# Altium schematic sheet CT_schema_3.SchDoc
size 400 x 230 mm
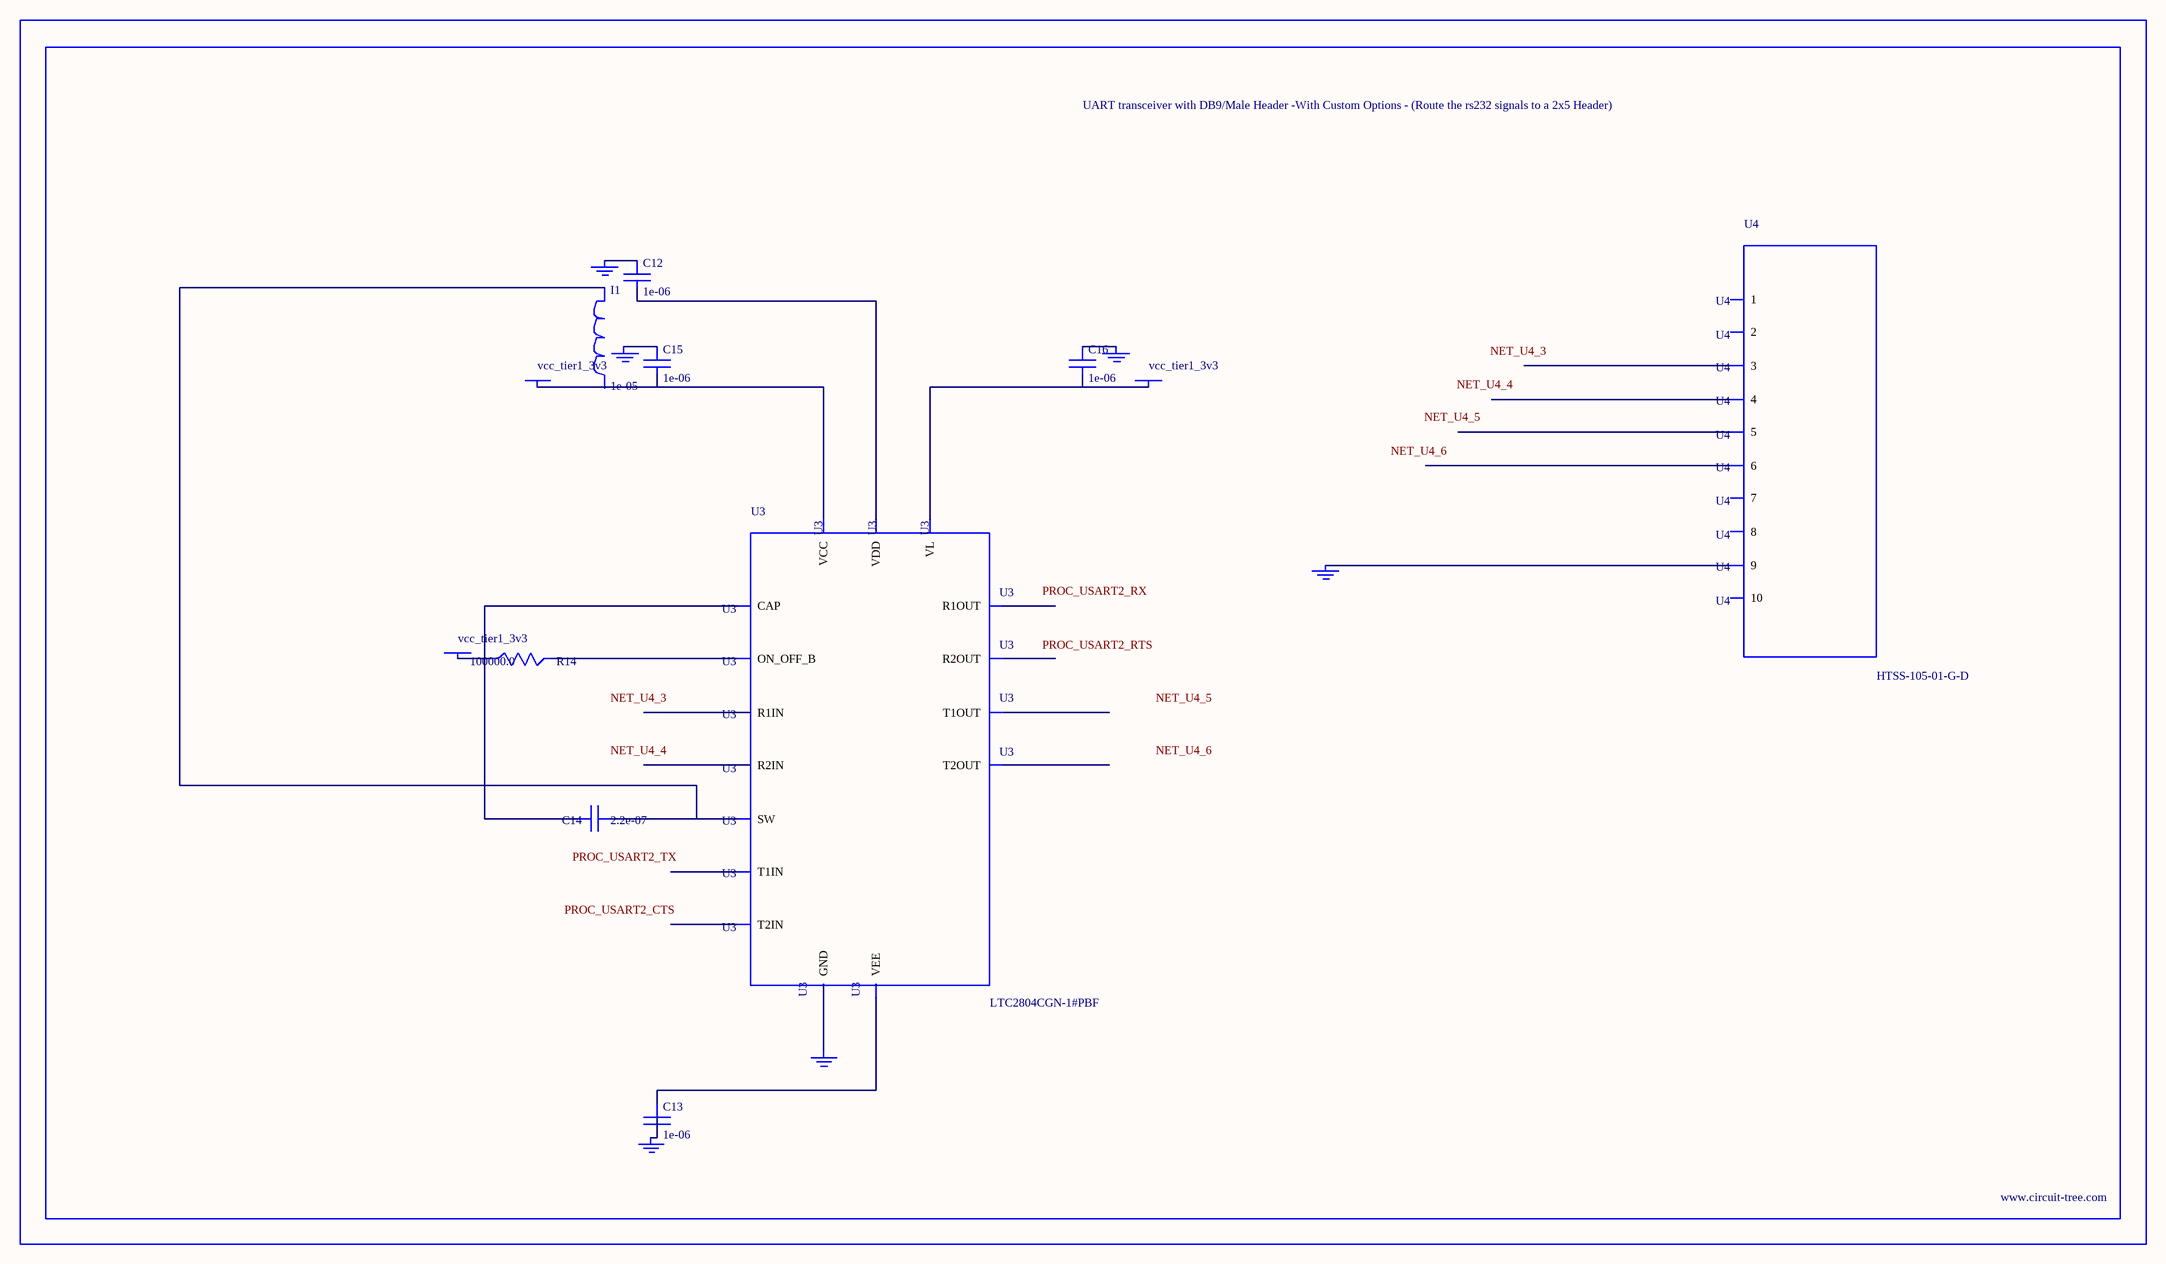
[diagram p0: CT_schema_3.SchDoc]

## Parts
BORDER2  (no value)
C12  1e-06  [C0603]
C13  1e-06  [C0603]
C14  2.2e-07  [C0603]
C15  1e-06  [C0603]
C16  1e-06  [C0603]
GND_INSTANCE_2_0  (no value)
GND_INSTANCE_2_1  (no value)
GND_INSTANCE_2_2  (no value)
GND_INSTANCE_2_3  (no value)
GND_INSTANCE_2_4  (no value)
GND_INSTANCE_2_5  (no value)
I1  1e-05  [L1210]
POWER_INSTANCE_2_0  vcc_tier1_3v3
POWER_INSTANCE_2_1  vcc_tier1_3v3
POWER_INSTANCE_2_2  vcc_tier1_3v3
R14  100000.0  [R0603]
U3  LTC2804CGN-1#PBF  [SSOP-16]
U4  HTSS-105-01-G-D  [HTSS-105-01-G-D]

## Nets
NetC12_1: C12.1 GND_INSTANCE_2_1.0(GND)
NetC12_2: C12.2 U3.6(VDD)
NetC13_1: C13.1 U3.9(VEE)
NetC13_2: C13.2 GND_INSTANCE_2_2.0(GND)
NetC14_1: C14.1 I1.1 U3.7(SW)
NetC14_2: C14.2 U3.10(CAP)
NetC15_1: C15.1 GND_INSTANCE_2_0.0(GND)
NetC15_2: C15.2 POWER_INSTANCE_2_0.0(PWR) U3.5(VCC)
NetC16_1: C16.1 GND_INSTANCE_2_3.0(GND)
NetC16_2: C16.2 POWER_INSTANCE_2_2.0(PWR) U3.12(VL)
NetGND_INSTANCE_2_4_0: GND_INSTANCE_2_4.0(GND) U3.8(GND)
NetGND_INSTANCE_2_5_0: GND_INSTANCE_2_5.0(GND) U4.9
NetPOWER_INSTANCE_2_1_0: POWER_INSTANCE_2_1.0(PWR) R14.1
NetR14_2: R14.2 U3.11(ON_OFF_B)

Not connected (* = marked no-connect by the designer): I1 2; U3 1(R1IN) 2(R2IN) 3(T1OUT) 4(T2OUT) 13(T2IN) 14(T1IN) 15(R2OUT) 16(R1OUT); U4 1 2 3 4 5 6 7 8 10

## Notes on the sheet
- Labels drawn without touching a wire or pin: NET_U4_3, NET_U4_4, NET_U4_5, NET_U4_6, PROC_USART2_CTS, PROC_USART2_RTS, PROC_USART2_RX, PROC_USART2_TX

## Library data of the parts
BORDER2 = BORDER_PAGE2
C12 C13 C15 C16 = C0603C105K3RACTU
C14 = C0603C224K3RAC
GND_INSTANCE_2_0-GND_INSTANCE_2_5 = GND
I1 = CBC3225T100MR
POWER_INSTANCE_2_0-POWER_INSTANCE_2_2 = PWR
R14 = RC0603JR-07100KL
